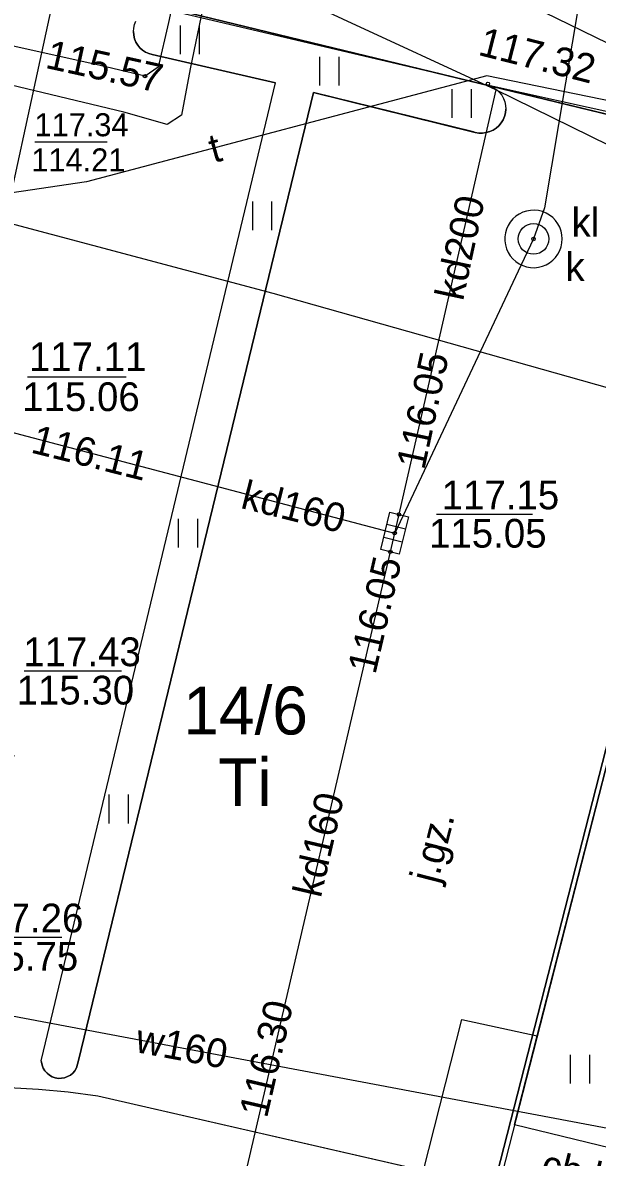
# Model space of a CAD drawing. Extents: x 6424617 to 6425697, y 5665845 to 5667190.
# Drawn here: x 6425390.51 to 6425405.51, y 5666331.53 to 5666361.13 of the extents above; entities that cross this region are included whole.
import ezdxf

# ---------------------------------------------------------------- set-up
doc = ezdxf.new("R2010")
doc.units = 0
for name, color, linetype in [('Warstwa 1', 7, 'Continuous'), ('Warstwa 10', 7, 'Continuous'), ('Warstwa 12', 7, 'Continuous'), ('Warstwa 13', 7, 'Continuous'), ('Warstwa 14', 7, 'Continuous'), ('Warstwa 15', 7, 'Continuous'), ('Warstwa 2', 7, 'Continuous'), ('Warstwa 22', 7, 'Continuous'), ('Warstwa 25', 7, 'Continuous'), ('Warstwa 4', 7, 'Continuous'), ('Warstwa 5', 7, 'Continuous'), ('Warstwa 6', 7, 'Continuous'), ('Warstwa 8', 7, 'Continuous'), ('Warstwa 9', 7, 'Continuous')]:
    doc.layers.add(name, color=color, linetype=linetype)

msp = doc.modelspace()

# ---------------------------------------------------------------- linework, layer by layer
at = {"layer": 'Warstwa 1'}
for p in [(6425384.34, 5666363.943), (6425384.34, 5666363.943), (6425395.066, 5666300.59), (6425395.066, 5666300.59)]:
    msp.add_line(p, (6425409.727, 5666357.777), dxfattribs=at)
at = {"layer": 'Warstwa 10'}
msp.add_lwpolyline([(6425441.845, 5666345.034), (6425435.644, 5666345.684), (6425416.754, 5666350.792), (6425414.426, 5666349.31), (6425409.689, 5666350.497), (6425397.042, 5666354.07), (6425390.053, 5666355.924), (6425382.597, 5666357.904), (6425376.603, 5666359.336), (6425374.869, 5666359.807), (6425368.783, 5666361.001), (6425351.183, 5666364.453), (6425348.415, 5666364.948)], dxfattribs=at)
at = {"layer": 'Warstwa 12'}
msp.add_line((6425400.216, 5666347.811), (6425396.307, 5666331.043), dxfattribs=at)
for points in [[(6425380.898, 5666313.781), (6425400.051, 5666402.067), (6425408.909, 5666440.823), (6425416.154, 5666473.488), (6425420.109, 5666487.161), (6425420.685, 5666489.264), (6425421.019, 5666490.41), (6425433.788, 5666544.17), (6425438.345, 5666557.965), (6425447.158, 5666555.689), (6425449.696, 5666562.969)], [(6425373.736, 5666374.755), (6425375.002, 5666374.56), (6425385.846, 5666370.306), (6425386.476, 5666369.999), (6425406.785, 5666360.113), (6425430.583, 5666354.786), (6425431.352, 5666354.657)], [(6425439.24, 5666333.418), (6425426.991, 5666336.388), (6425420.09, 5666338.051), (6425419.57, 5666338.3), (6425418.724, 5666338.388), (6425410.008, 5666340.443), (6425409.32, 5666340.611), (6425409.518, 5666341.279), (6425413.167, 5666353.556), (6425413.365, 5666354.223), (6425412.738, 5666354.531), (6425402.856, 5666359.381), (6425386.87, 5666366.77), (6425385.858, 5666367.253), (6425385.32, 5666367.51), (6425376.142, 5666372.493), (6425375.647, 5666372.869), (6425375.505, 5666373.611), (6425375.267, 5666374.564), (6425373.736, 5666374.755)], [(6425406.67, 5666371.43), (6425404.13, 5666356.3), (6425403.84, 5666355.49), (6425403.44, 5666354.65), (6425400.22, 5666347.81)], [(6425432.15, 5666358.51), (6425420.34, 5666360.73), (6425408.57, 5666362.91), (6425396.57, 5666365.25), (6425395.48, 5666365.42), (6425395.14, 5666365.16), (6425394.95, 5666364.09), (6425394.31, 5666361.14), (6425394.04, 5666359.97), (6425393.7, 5666359.74), (6425392.53, 5666360.02), (6425389.99, 5666360.58), (6425388.39, 5666360.95), (6425386.07, 5666361.48), (6425384.57, 5666361.92), (6425383.3, 5666362.25), (6425382.92, 5666362.02), (6425380.46, 5666352.06), (6425378.87, 5666345.74), (6425377.99, 5666342.16), (6425377.55, 5666340.46), (6425377.17, 5666340.22), (6425375.82, 5666340.56), (6425306.003, 5666358.105)], [(6425395.54, 5666363.12), (6425394.88, 5666359.93), (6425394.65, 5666358.72), (6425394.28, 5666358.48), (6425393.15, 5666358.8), (6425389.76, 5666359.61), (6425388.11, 5666360.01), (6425385.86, 5666360.57), (6425385.04, 5666360.8), (6425383.75, 5666361.13), (6425383.43, 5666360.89), (6425383.12, 5666359.65), (6425381.19, 5666351.86), (6425379.61, 5666345.61), (6425378.3, 5666340.14), (6425378.07, 5666339.17), (6425377.68, 5666338.94), (6425375.53, 5666339.45), (6425305.977, 5666356.006)], [(6425442.733, 5666353.01), (6425442.294, 5666353.165), (6425426.57, 5666356.254), (6425415.105, 5666358.333), (6425410.252, 5666358.181), (6425402.62, 5666359.743), (6425392.176, 5666356.979), (6425386.816, 5666356.193), (6425378.162, 5666354.247), (6425377.402, 5666354.057)], [(6425402.856, 5666359.381), (6425400.216, 5666347.811)], [(6425389.519, 5666350.63), (6425400.216, 5666347.811)], [(6425372.086, 5666347.268), (6425373.194, 5666346.946), (6425381.905, 5666344.561), (6425389.18, 5666342.374), (6425390.275, 5666342.01), (6425389.074, 5666338.625), (6425388.098, 5666335.616), (6425410.349, 5666331.428), (6425437.797, 5666326.979)]]:
    msp.add_lwpolyline(points, dxfattribs=at)
at = {"layer": 'Warstwa 14'}
for p, q in [((6425392.715, 5666358.013), (6425390.82, 5666358.013)), ((6425393.212, 5666351.88), (6425390.637, 5666351.88)), ((6425401.312, 5666348.31), (6425403.813, 5666348.31)), ((6425390.548, 5666344.217), (6425393.084, 5666344.217)), ((6425389.082, 5666337.271), (6425391.528, 5666337.271))]:
    msp.add_line(p, q, dxfattribs=at)
for centre in [(6425393.7, 5666359.74), (6425403.84, 5666355.49), (6425400.327, 5666348.299), (6425400.216, 5666347.811), (6425400.102, 5666347.324)]:
    msp.add_circle(centre, 0.045, dxfattribs=at)
at = {"layer": 'Warstwa 2'}
msp.add_lwpolyline([(6425409.889, 5666357.905), (6425401.391, 5666324.767)], dxfattribs=at)
at = {"layer": 'Warstwa 22'}
msp.add_lwpolyline([(6425404.59, 5666355.49), (6425404.583, 5666355.594), (6425404.561, 5666355.697), (6425404.525, 5666355.795), (6425404.476, 5666355.887), (6425404.415, 5666355.972), (6425404.342, 5666356.047), (6425404.259, 5666356.112), (6425404.169, 5666356.164), (6425404.072, 5666356.203), (6425403.97, 5666356.229), (6425403.866, 5666356.24), (6425403.762, 5666356.236), (6425403.659, 5666356.218), (6425403.559, 5666356.185), (6425403.465, 5666356.14), (6425403.378, 5666356.081), (6425403.3, 5666356.011), (6425403.233, 5666355.931), (6425403.178, 5666355.842), (6425403.135, 5666355.747), (6425403.106, 5666355.646), (6425403.092, 5666355.542), (6425403.092, 5666355.438), (6425403.106, 5666355.334), (6425403.135, 5666355.233), (6425403.178, 5666355.138), (6425403.233, 5666355.049), (6425403.3, 5666354.969), (6425403.378, 5666354.899), (6425403.465, 5666354.84), (6425403.559, 5666354.795), (6425403.659, 5666354.762), (6425403.762, 5666354.744), (6425403.866, 5666354.74), (6425403.97, 5666354.751), (6425404.072, 5666354.777), (6425404.169, 5666354.816), (6425404.259, 5666354.868), (6425404.342, 5666354.933), (6425404.415, 5666355.008), (6425404.476, 5666355.093), (6425404.525, 5666355.185), (6425404.561, 5666355.283), (6425404.583, 5666355.386)], close=True, dxfattribs=at)
at = {"layer": 'Warstwa 25'}
msp.add_circle((6425402.65, 5666359.54), 0.045, dxfattribs=at)
at = {"layer": 'Warstwa 4'}
for p, q in [((6425400.501, 5666347.92), (6425400.016, 5666348.041)), ((6425400.416, 5666347.581), (6425399.931, 5666347.702))]:
    msp.add_line(p, q, dxfattribs=at)
msp.add_lwpolyline([(6425400.579, 5666348.236), (6425400.338, 5666347.265), (6425399.853, 5666347.386), (6425400.094, 5666348.357)], close=True, dxfattribs=at)
msp.add_circle((6425403.84, 5666355.49), 0.4, dxfattribs=at)
at = {"layer": 'Warstwa 5'}
for p, q in [((6425394.16, 5666361.5), (6425402.63, 5666359.51)), ((6425393.404, 5666360.992), (6425393.424, 5666361.083)), ((6425393.424, 5666361.083), (6425393.458, 5666361.17)), ((6425393.397, 5666360.899), (6425393.404, 5666360.992)), ((6425393.397, 5666360.899), (6425393.405, 5666360.806)), ((6425393.405, 5666360.806), (6425393.426, 5666360.716)), ((6425394.625, 5666360.311), (6425394.625, 5666361.061)), ((6425395.125, 5666360.311), (6425395.125, 5666361.061)), ((6425393.426, 5666360.716), (6425393.461, 5666360.629)), ((6425393.461, 5666360.629), (6425393.509, 5666360.549)), ((6425393.509, 5666360.549), (6425393.568, 5666360.477)), ((6425393.568, 5666360.477), (6425393.638, 5666360.415)), ((6425393.638, 5666360.415), (6425393.716, 5666360.364)), ((6425393.716, 5666360.364), (6425393.8, 5666360.325)), ((6425393.8, 5666360.325), (6425393.89, 5666360.3)), ((6425393.89, 5666360.3), (6425397.11, 5666359.56)), ((6425398.266, 5666359.496), (6425398.266, 5666360.246)), ((6425398.766, 5666359.496), (6425398.766, 5666360.246)), ((6425391.05, 5666334.3), (6425397.11, 5666359.56)), ((6425391.96, 5666334.05), (6425398.1, 5666359.31)), ((6425398.1, 5666359.31), (6425402.32, 5666358.27)), ((6425401.719, 5666358.651), (6425401.719, 5666359.401)), ((6425402.219, 5666358.651), (6425402.219, 5666359.401)), ((6425402.63, 5666359.51), (6425402.721, 5666359.48)), ((6425402.721, 5666359.48), (6425402.806, 5666359.437)), ((6425402.806, 5666359.437), (6425402.884, 5666359.382)), ((6425402.884, 5666359.382), (6425402.953, 5666359.315)), ((6425402.953, 5666359.315), (6425403.011, 5666359.239)), ((6425403.011, 5666359.239), (6425403.057, 5666359.156)), ((6425403.057, 5666359.156), (6425403.091, 5666359.066)), ((6425403.091, 5666359.066), (6425403.11, 5666358.972)), ((6425403.083, 5666358.689), (6425403.106, 5666358.782)), ((6425403.106, 5666358.782), (6425403.115, 5666358.877)), ((6425403.11, 5666358.972), (6425403.115, 5666358.877)), ((6425402.864, 5666358.382), (6425402.935, 5666358.445)), ((6425402.935, 5666358.445), (6425402.997, 5666358.519)), ((6425402.997, 5666358.519), (6425403.046, 5666358.6)), ((6425403.046, 5666358.6), (6425403.083, 5666358.689)), ((6425402.32, 5666358.27), (6425402.414, 5666358.254)), ((6425402.414, 5666358.254), (6425402.51, 5666358.251)), ((6425402.51, 5666358.251), (6425402.605, 5666358.264)), ((6425402.605, 5666358.264), (6425402.697, 5666358.29)), ((6425402.697, 5666358.29), (6425402.784, 5666358.329)), ((6425402.784, 5666358.329), (6425402.864, 5666358.382)), ((6425405.171, 5666339.506), (6425409.712, 5666357.212)), ((6425396.511, 5666355.721), (6425396.511, 5666356.471)), ((6425397.011, 5666355.721), (6425397.011, 5666356.471)), ((6425394.577, 5666347.436), (6425394.577, 5666348.186)), ((6425395.077, 5666347.436), (6425395.077, 5666348.186)), ((6425392.767, 5666340.24), (6425392.767, 5666340.99)), ((6425393.267, 5666340.24), (6425393.267, 5666340.99)), ((6425403.936, 5666334.692), (6425405.171, 5666339.506)), ((6425403.344, 5666332.384), (6425403.936, 5666334.692)), ((6425390.993, 5666334.048), (6425391.05, 5666334.3)), ((6425404.809, 5666333.449), (6425404.809, 5666334.199)), ((6425405.309, 5666333.449), (6425405.309, 5666334.199)), ((6425390.993, 5666334.048), (6425390.996, 5666334.011)), ((6425390.996, 5666334.011), (6425391.013, 5666333.93)), ((6425391.013, 5666333.93), (6425391.044, 5666333.853)), ((6425391.044, 5666333.853), (6425391.087, 5666333.783)), ((6425391.87, 5666333.787), (6425391.912, 5666333.858)), ((6425391.912, 5666333.858), (6425391.96, 5666334.05)), ((6425391.087, 5666333.783), (6425391.142, 5666333.72)), ((6425391.142, 5666333.72), (6425391.206, 5666333.669)), ((6425391.206, 5666333.669), (6425391.278, 5666333.628)), ((6425391.278, 5666333.628), (6425391.356, 5666333.601)), ((6425391.356, 5666333.601), (6425391.438, 5666333.587)), ((6425391.438, 5666333.587), (6425391.521, 5666333.588)), ((6425391.521, 5666333.588), (6425391.602, 5666333.602)), ((6425391.602, 5666333.602), (6425391.68, 5666333.631)), ((6425391.68, 5666333.631), (6425391.752, 5666333.672)), ((6425391.752, 5666333.672), (6425391.816, 5666333.724)), ((6425391.816, 5666333.724), (6425391.87, 5666333.787)), ((6425403.344, 5666332.384), (6425406.64, 5666331.58))]:
    msp.add_line(p, q, dxfattribs=at)
at = {"layer": 'Warstwa 6'}
for points in [[(6425444.939, 5666358.836), (6425386.434, 5666372.619), (6425384.34, 5666363.943), (6425409.727, 5666357.777), (6425442.84, 5666349.471)], [(6425394.16, 5666361.5), (6425402.63, 5666359.51), (6425402.721, 5666359.48), (6425402.806, 5666359.437), (6425402.884, 5666359.382), (6425402.953, 5666359.315), (6425403.011, 5666359.239), (6425403.057, 5666359.156), (6425403.091, 5666359.066), (6425403.11, 5666358.972), (6425403.115, 5666358.877), (6425403.106, 5666358.782), (6425403.083, 5666358.689), (6425403.046, 5666358.6), (6425402.997, 5666358.519), (6425402.935, 5666358.445), (6425402.864, 5666358.382), (6425402.784, 5666358.329), (6425402.697, 5666358.29), (6425402.605, 5666358.264), (6425402.51, 5666358.251), (6425402.414, 5666358.254), (6425402.32, 5666358.27), (6425402.273, 5666358.282)], [(6425402.273, 5666358.282), (6425398.1, 5666359.31), (6425391.96, 5666334.05), (6425391.912, 5666333.858), (6425391.87, 5666333.787), (6425391.816, 5666333.724), (6425391.752, 5666333.672), (6425391.68, 5666333.631), (6425391.602, 5666333.602), (6425391.521, 5666333.588), (6425391.438, 5666333.587), (6425391.356, 5666333.601), (6425391.278, 5666333.628), (6425391.206, 5666333.669), (6425391.142, 5666333.72), (6425391.087, 5666333.783), (6425391.044, 5666333.853), (6425391.013, 5666333.93), (6425390.996, 5666334.011), (6425390.993, 5666334.048), (6425391.05, 5666334.3), (6425397.11, 5666359.56), (6425393.89, 5666360.3), (6425393.8, 5666360.325), (6425393.716, 5666360.364), (6425393.638, 5666360.415), (6425393.568, 5666360.477), (6425393.509, 5666360.549), (6425393.461, 5666360.629), (6425393.426, 5666360.716), (6425393.405, 5666360.806), (6425393.397, 5666360.899), (6425393.404, 5666360.992), (6425393.424, 5666361.083), (6425393.458, 5666361.17)], [(6425442.84, 5666349.471), (6425409.727, 5666357.777), (6425395.066, 5666300.59), (6425404.21, 5666298.38), (6425405.211, 5666295.977), (6425410.032, 5666305.93), (6425432.042, 5666301.313)]]:
    msp.add_lwpolyline(points, dxfattribs=at)
msp.add_lwpolyline([(6425372.318, 5666314.174), (6425391.459, 5666309.994), (6425389.007, 5666299.923), (6425392.846, 5666298.986), (6425393.331, 5666301.001), (6425395.066, 5666300.59), (6425409.727, 5666357.777), (6425384.34, 5666363.943)], close=True, dxfattribs=at)
at = {"layer": 'Warstwa 8'}
for p, q in [((6425394.16, 5666361.5), (6425402.63, 5666359.51)), ((6425393.404, 5666360.992), (6425393.424, 5666361.083)), ((6425393.424, 5666361.083), (6425393.458, 5666361.17)), ((6425393.397, 5666360.899), (6425393.404, 5666360.992)), ((6425393.397, 5666360.899), (6425393.405, 5666360.806)), ((6425393.405, 5666360.806), (6425393.426, 5666360.716)), ((6425393.426, 5666360.716), (6425393.461, 5666360.629)), ((6425393.461, 5666360.629), (6425393.509, 5666360.549)), ((6425393.509, 5666360.549), (6425393.568, 5666360.477)), ((6425393.568, 5666360.477), (6425393.638, 5666360.415)), ((6425393.638, 5666360.415), (6425393.716, 5666360.364)), ((6425393.716, 5666360.364), (6425393.8, 5666360.325)), ((6425393.8, 5666360.325), (6425393.89, 5666360.3)), ((6425393.89, 5666360.3), (6425397.11, 5666359.56)), ((6425391.05, 5666334.3), (6425397.11, 5666359.56)), ((6425391.96, 5666334.05), (6425398.1, 5666359.31)), ((6425398.1, 5666359.31), (6425402.32, 5666358.27)), ((6425402.63, 5666359.51), (6425409.889, 5666357.905)), ((6425402.63, 5666359.51), (6425402.721, 5666359.48)), ((6425402.63, 5666359.51), (6425409.889, 5666357.905)), ((6425402.721, 5666359.48), (6425402.806, 5666359.437)), ((6425402.806, 5666359.437), (6425402.884, 5666359.382)), ((6425402.884, 5666359.382), (6425402.953, 5666359.315)), ((6425402.953, 5666359.315), (6425403.011, 5666359.239)), ((6425403.011, 5666359.239), (6425403.057, 5666359.156)), ((6425403.057, 5666359.156), (6425403.091, 5666359.066)), ((6425403.091, 5666359.066), (6425403.11, 5666358.972)), ((6425403.083, 5666358.689), (6425403.106, 5666358.782)), ((6425403.106, 5666358.782), (6425403.115, 5666358.877)), ((6425403.11, 5666358.972), (6425403.115, 5666358.877)), ((6425402.864, 5666358.382), (6425402.935, 5666358.445)), ((6425402.935, 5666358.445), (6425402.997, 5666358.519)), ((6425402.997, 5666358.519), (6425403.046, 5666358.6)), ((6425403.046, 5666358.6), (6425403.083, 5666358.689)), ((6425402.32, 5666358.27), (6425402.414, 5666358.254)), ((6425402.414, 5666358.254), (6425402.51, 5666358.251)), ((6425402.51, 5666358.251), (6425402.605, 5666358.264)), ((6425402.605, 5666358.264), (6425402.697, 5666358.29)), ((6425402.697, 5666358.29), (6425402.784, 5666358.329)), ((6425402.784, 5666358.329), (6425402.864, 5666358.382)), ((6425403.936, 5666334.692), (6425409.711, 5666357.212)), ((6425400.97, 5666331.18), (6425401.97, 5666335.12)), ((6425401.97, 5666335.12), (6425403.936, 5666334.692)), ((6425390.993, 5666334.048), (6425391.05, 5666334.3)), ((6425390.993, 5666334.048), (6425390.996, 5666334.011)), ((6425390.996, 5666334.011), (6425391.013, 5666333.93)), ((6425391.013, 5666333.93), (6425391.044, 5666333.853)), ((6425391.044, 5666333.853), (6425391.087, 5666333.783)), ((6425391.87, 5666333.787), (6425391.912, 5666333.858)), ((6425391.912, 5666333.858), (6425391.96, 5666334.05)), ((6425391.087, 5666333.783), (6425391.142, 5666333.72)), ((6425391.142, 5666333.72), (6425391.206, 5666333.669)), ((6425391.206, 5666333.669), (6425391.278, 5666333.628)), ((6425391.278, 5666333.628), (6425391.356, 5666333.601)), ((6425391.356, 5666333.601), (6425391.438, 5666333.587)), ((6425391.438, 5666333.587), (6425391.521, 5666333.588)), ((6425391.521, 5666333.588), (6425391.602, 5666333.602)), ((6425391.602, 5666333.602), (6425391.68, 5666333.631)), ((6425391.68, 5666333.631), (6425391.752, 5666333.672)), ((6425391.752, 5666333.672), (6425391.816, 5666333.724)), ((6425391.816, 5666333.724), (6425391.87, 5666333.787)), ((6425390.142, 5666333.352), (6425390.921, 5666333.307)), ((6425390.142, 5666333.352), (6425390.921, 5666333.307)), ((6425390.921, 5666333.307), (6425391.697, 5666333.233)), ((6425390.921, 5666333.307), (6425391.697, 5666333.233)), ((6425391.697, 5666333.233), (6425392.47, 5666333.13)), ((6425391.697, 5666333.233), (6425392.47, 5666333.13)), ((6425392.47, 5666333.13), (6425400.9, 5666331.2)), ((6425392.47, 5666333.13), (6425400.97, 5666331.18))]:
    msp.add_line(p, q, dxfattribs=at)
at = {"layer": 'Warstwa 9'}
for p, q in [((6425400.97, 5666331.18), (6425401.97, 5666335.12)), ((6425401.97, 5666335.12), (6425403.936, 5666334.692)), ((6425403.344, 5666332.384), (6425403.936, 5666334.692)), ((6425403.344, 5666332.384), (6425406.64, 5666331.58))]:
    msp.add_line(p, q, dxfattribs=at)

# ---------------------------------------------------------------- texts
at = {"layer": 'Warstwa 13'}
for s, rotation, p in [('t', 15.5157, (6425395.49, 5666357.466)), ('kd200', 77.8363, (6425401.998, 5666353.851)), ('kd160', 345.9233, (6425396.168, 5666348.474)), ('kd160', 76.9482, (6425398.286, 5666338.273)), ('w160', 349.3381, (6425393.417, 5666334.278))]:
    msp.add_text(s, height=0.75, rotation=rotation, dxfattribs=at).set_placement(p)
at = {"layer": 'Warstwa 14'}
for s, rotation, p in [('115.57', 347.5677, (6425391.071, 5666359.958)), ('116.05', 77.8363, (6425400.988, 5666349.442)), ('116.11', 345.9233, (6425390.692, 5666349.922)), ('116.05', 76.9482, (6425399.712, 5666344.105)), ('116.30', 76.9482, (6425396.881, 5666332.526))]:
    msp.add_text(s, height=0.75, rotation=rotation, dxfattribs=at).set_placement(p)
for s, height, p in [('114.21', 0.6, (6425390.734, 5666357.252)), ('115.06', 0.75, (6425390.495, 5666350.998)), ('115.05', 0.75, (6425401.114, 5666347.435)), ('115.30', 0.75, (6425390.348, 5666343.342)), ('115.75', 0.75, (6425388.889, 5666336.396))]:
    msp.add_text(s, height=height, dxfattribs=at).set_placement(p)
at = {"layer": 'Warstwa 15'}
for s, height, p in [('117.34', 0.6, (6425390.816, 5666358.17)), ('117.11', 0.75, (6425390.671, 5666352.041)), ('117.15', 0.75, (6425401.443, 5666348.435)), ('117.43', 0.75, (6425390.523, 5666344.342)), ('14/6', 1.25, (6425394.699, 5666342.56)), ('117.26', 0.75, (6425389.023, 5666337.396))]:
    msp.add_text(s, height=height, dxfattribs=at).set_placement(p)
at = {"layer": 'Warstwa 2'}
msp.add_text('Ti', height=1.25, dxfattribs=at).set_placement((6425395.613, 5666340.69))
at = {"layer": 'Warstwa 22'}
msp.add_text('kl', height=0.75, dxfattribs=at).set_placement((6425404.833, 5666355.55))
at = {"layer": 'Warstwa 25'}
msp.add_text('117.32', height=0.75, rotation=345.6998, dxfattribs=at).set_placement((6425402.367, 5666360.298))
at = {"layer": 'Warstwa 5'}
msp.add_text('k', height=0.75, dxfattribs=at).set_placement((6425404.676, 5666354.389))
at = {"layer": 'Warstwa 8'}
msp.add_text('j.gz.', height=0.75, rotation=75.619, dxfattribs=at).set_placement((6425401.332, 5666338.644))
at = {"layer": 'Warstwa 9'}
msp.add_text('ch.kp.', height=0.75, rotation=346.29, dxfattribs=at).set_placement((6425403.99, 5666331.011))

doc.saveas('drawing.dxf')
